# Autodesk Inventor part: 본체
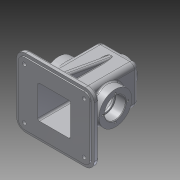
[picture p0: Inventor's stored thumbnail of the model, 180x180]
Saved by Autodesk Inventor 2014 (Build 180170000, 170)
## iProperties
Created: 2016-06
Part Number: 본체
Material: Aluminum 6061
Document SubType Name: Modeling
Designer: user
Density: 2.71 g/cm^3
Appearance: Aluminum - Flat
Mass: 810.193 g
Surface Area: 906.022 cm^2
Volume: 298.964 cm^3
Author: user
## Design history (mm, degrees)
sketch "Sketch1"
  geometry: L1 (65, -57.5)-(-65, -57.5); L2 (-65, -57.5)-(-65, 57.5); L3 (-65, 57.5)-(65, 57.5); L4 (65, 57.5)-(65, -57.5); 3 further points
  constraints: 8 end point, 2 midpoint, 2 parallel, 1 horizontal, 1 horizontal alignment, 1 perpendicular, 1 vertical alignment
  dimensions: "d0" = 130 distance of L1.start L1.end; "d1" = 115 distance of L1.end L2.end
extrude "Extrusion1" new body sketch "Sketch1" distance "d2" = 8; taper "d3" = 0 deg
fillet "Fillet1" dims "d4" = 15
sketch "Sketch2"
  geometry: L1 (-65, 42.5)-(-65, -42.5) reference; L2 (-50, -57.5)-(50, -57.5) reference; L3 (65, -42.5)-(65, 42.5) reference; L4 (50, 57.5)-(-50, 57.5) reference; L5 (-60, 42.5)-(-60, -42.5); L6 (-50, -52.5)-(50, -52.5); L7 (60, -42.5)-(60, 42.5); L8 (50, 52.5)-(-50, 52.5); A1 r 15 centre (-50, 42.5) between (-50, 57.5) and (-65, 42.5) reference; A2 r 15 centre (-50, -42.5) between (-65, -42.5) and (-50, -57.5) reference; A3 r 15 centre (50, -42.5) between (50, -57.5) and (65, -42.5) reference; A4 r 15 centre (50, 42.5) between (65, 42.5) and (50, 57.5) reference; A5 r 10 centre (-50, 42.5) between (-50, 52.5) and (-60, 42.5); A6 r 10 centre (-50, -42.5) between (-60, -42.5) and (-50, -52.5); A7 r 10 centre (50, -42.5) between (50, -52.5) and (60, -42.5); A8 r 10 centre (50, 42.5) between (60, 42.5) and (50, 52.5); 1 further point
  constraints: 8 end point, 8 point on circle, 4 centre point, 7 other
  dimensions: "d5" = 5 distance between parallel lines of L4 L8
extrude "Extrusion2" join sketch "Sketch2" distance "d6" = 2; taper "d7" = 0 deg
sketch "Sketch3"
  geometry: C1 r 7.5 at (-50, 42.5); C2 r 7.5 at (50, 42.5); C3 r 7.5 at (50, -42.5); C4 r 7.5 at (-50, -42.5); A1 r 15 centre (-50, -42.5) between (-65, -42.5) and (-50, -57.5) reference; A2 r 15 centre (50, -42.5) between (50, -57.5) and (65, -42.5) reference; A3 r 15 centre (50, 42.5) between (65, 42.5) and (50, 57.5) reference; A4 r 15 centre (-50, 42.5) between (-50, 57.5) and (-65, 42.5) reference; 1 further point
  constraints: 4 centre point, 4 coincident, 3 equal radius
  dimensions: "d8" = 7.5 radius of C1
extrude "Extrusion3" join sketch "Sketch3" distance "d9" = 3; taper "d10" = 0 deg
fillet "Fillet2" dims "d11" = 3
hole "Hole1" diameter "d14" = 6; stored, may be unused: countersink angle "d18" = 90 deg, drill point angle "d20" = 118 deg; dims "d12" = 10, "d13" = 10, "d15" = 6, "d16" = 4, "d17" = 2, "d19" = 8
pattern_linear "Rectangular Pattern1" dims "d23" = 85
sketch "Sketch4"
  geometry: L1 (-32.5, 32.5)-(32.5, 32.5); L2 (32.5, 32.5)-(32.5, -32.5); L3 (32.5, -32.5)-(-32.5, -32.5); L4 (-32.5, -32.5)-(-32.5, 32.5); 3 further points
  constraints: 8 end point, 2 midpoint, 2 parallel, 1 horizontal, 1 horizontal alignment, 1 perpendicular, 1 vertical alignment
  dimensions: "d27" = 65 distance of L1.start L1.end; "d28" = 65 distance of L1.end L2.end
extrude "Extrusion4" join sketch "Sketch4" distance "d29" = 100; taper "d30" = 0 deg
fillet "Fillet6" dims "d42" = 8
sketch "Sketch6"
  geometry: L1 (75, -10)-(-10, -10) reference; C1 r 27.5 at (32.5, 45); 2 further points
  constraints: 1 centre point, 1 midpoint, 1 vertical alignment
  dimensions: "d37" = 27.5 radius of C1; "d38" = 55 distance from line of C1.centre L1
extrude "Extrusion6" join sketch "Sketch6" distance "d39" = 15; taper "d40" = 0 deg
mirror "Mirror1"
fillet "Fillet5" dims "d41" = 3
fillet "Fillet7" dims "d43" = 8
hole "Hole2" diameter "d46" = 30; stored, may be unused: countersink angle "d50" = 90 deg, drill point angle "d52" = 0 deg; dims "d47" = 6, "d48" = 35, "d49" = 17, "d51" = 20, "d53" = 10, "d54" = 10
mirror "Mirror2"
sketch "Sketch7"
  geometry: L1 (-27.5, 27.5)-(27.5, 27.5); L2 (27.5, 27.5)-(27.5, -27.5); L3 (27.5, -27.5)-(-27.5, -27.5); L4 (-27.5, -27.5)-(-27.5, 27.5); 3 further points
  constraints: 8 end point, 2 midpoint, 2 parallel, 2 perpendicular, 1 horizontal, 1 horizontal alignment, 1 vertical alignment
  dimensions: "d55" = 55 distance of L1.start L1.end
extrude "Extrusion7" cut sketch "Sketch7" distance "d56" = 105; taper "d57" = 0 deg
fillet "Fillet8" dims "d58" = 3
fillet "Fillet9" dims "d59" = 3
workplane "Work Plane1"
sketch "Sketch16"
  geometry: C1 r 20 at (0, 0); 1 further point
  constraints: 1 centre point, 1 coincident
  dimensions: "d130" = 20 radius of C1
fillet "Fillet10" dims "d63" = 1
sketch "Sketch9" dims "d73" = 42
  geometry: C1 r 17.5 at (0, 0) reference; C2 r 27.5 at (0, 0) reference; 3 further points
  constraints: 2 vertical alignment, 1 coincident, 2 other
hole "Hole4" sketch "Sketch9" at (0, 21) diameter "d74" = 3.242; stored, may be unused: countersink angle "d78" = 90 deg, drill point angle "d80" = 118 deg; dims "d75" = 8, "d76" = 35, "d77" = 17, "d79" = 10
pattern_circular "Circular Pattern1" dims angle "d82" = 360 deg
mirror "Mirror3"
sketch "Sketch11"
  geometry: L1 (5, -57.5)-(0, -57.5) reference; L2 (8, -53)-(8, -32) reference; L3 (8, -47.5)-(93.069, -32.5); L4 (100, -32.5)-(8, -32.5) reference; 2 further points
  constraints: 2 end point, 2 point on line
  dimensions: "d95" = 10 distance from line of L1 L3.start; "d96" = 10 deg angle of L3 L1
feature "Rib1" sketch "Sketch11" dims "d97" = 1, "d98" = 10, "d99" = 0, "d100" = 0, "d101" = 1, "d102" = 1
fillet "Fillet11" dims "d103" = 3
extrude "Extrusion9" join sketch "Sketch16" distance "d131" = 10; taper "d132" = 5 deg
mirror "Mirror4"
sketch "Sketch13"
  geometry: L1 (-32.5, 47)-(-32.5, -44) reference; L2 (-20, 65)-(20, 65) reference; 3 further points
  constraints: 1 other
  dimensions: "d157" = 26 distance from line of point (0, 39) L2; "d158" = 32.5 distance from line of point (0, 39) L1
emboss "Emboss1" sketch "Sketch13" dims "d107" = 0.5, "d108" = 0
sketch "Sketch14"
  geometry: L1 (42.5, 25.5)-(42.5, 8); L2 (27.5, -2)-(27.5, 100) reference; L3 (47.5, 25.5)-(35.5, 25.5) reference; L4 (60.5, 8)-(39.5, 8) reference; 1 further point
  constraints: 2 end point, 2 point on line, 1 vertical
  dimensions: "d109" = 15 distance between parallel lines of L2 L1
feature "Rib2" sketch "Sketch14" dims "d111" = 1, "d112" = 6, "d113" = 0, "d114" = 0, "d115" = 1, "d116" = 1
fillet "Fillet13" dims "d117" = 3
mirror "Mirror5"
chamfer "Chamfer2" distance "d122" = 1; stored, may be unused: second distance "d123" = 2, angle "d124" = 45 deg
chamfer "Chamfer3" distance "d125" = 1; stored, may be unused: second distance "d126" = 2, angle "d127" = 45 deg
fillet "Fillet15" dims "d128" = 0.3
sketch "Sketch17" dims "d133" = 14.5
  geometry: 3 further points
  constraints: 3 vertical alignment, 1 coincident, 2 other
hole "Hole6" sketch "Sketch17" at (0, 14.5) diameter "d134" = 2.459; stored, may be unused: countersink angle "d138" = 90 deg, drill point angle "d140" = 118 deg; dims "d135" = 7, "d136" = 35, "d137" = 17, "d139" = 9
pattern_circular "Circular Pattern3" dims angle "d142" = 360 deg
hole "Hole7" diameter "d146" = 21; stored, may be unused: countersink angle "d150" = 90 deg, drill point angle "d152" = 118 deg; dims "d144" = 10, "d145" = 10, "d147" = 21, "d148" = 35, "d149" = 17, "d151" = 9
chamfer "Chamfer4" distance "d153" = 1; stored, may be unused: second distance "d154" = 2, angle "d155" = 45 deg
fillet "Fillet16" dims "d156" = 3
fillet "Fillet17" dims "d159" = 1
body "Solid1"
